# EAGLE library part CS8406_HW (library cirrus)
DIGITAL AUDIO INTERFACE TRANSMITTER (Hardware Mode) 192 kHz, AES3, S/PDIF-compatible Transmitter
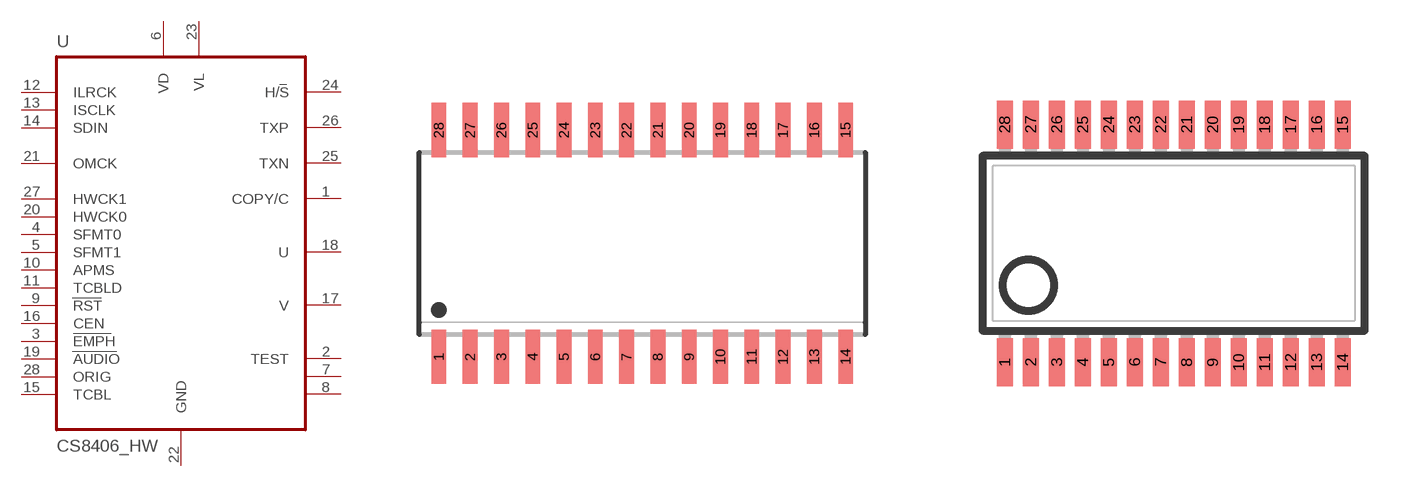
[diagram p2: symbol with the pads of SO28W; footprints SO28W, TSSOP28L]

Designator prefix U

## CS8406_HW-CSS  [SO28W]
1  COPY/C  in
2  TEST
3  EMPH  in
4  SFMT0  in
5  SFMT1  in
6  VD  pwr
7  TEST
8  TEST
9  RST  in
10  APMS  in
11  TCBLD  in
12  ILRCK
13  ISCLK
14  SDIN  in
15  TCBL
16  CEN  in
17  V  in
18  U  in
19  AUDIO  in
20  HWCK0  in
21  OMCK  in
22  GND  pwr
23  VL  pwr
24  H/S  in
25  TXN  out
26  TXP  out
27  HWCK1  in
28  ORIG  in

## CS8406_HW-CZZ  [TSSOP28L]
Pads as for SO28W

## Footprint SO28W (pad centres in mm)
SMALL OUTLINE INTEGRATED CIRCUIT wide body 7.5 mm/JEDEC MO-119AB
smd 0.6 x 2.2: 1 -8.255,-4.6; 2 -6.985,-4.6; 3 -5.715,-4.6; 4 -4.445,-4.6; 5 -3.175,-4.6; 6 -1.905,-4.6; 7 -0.635,-4.6; 8 0.635,-4.6; 9 1.905,-4.6; 10 3.175,-4.6; 11 4.445,-4.6; 12 5.715,-4.6; 13 6.985,-4.6; 14 8.255,-4.6; 15 8.255,4.6; 16 6.985,4.6; 17 5.715,4.6; 18 4.445,4.6; 19 3.175,4.6; 20 1.905,4.6; 21 0.635,4.6; 22 -0.635,4.6; 23 -1.905,4.6; 24 -3.175,4.6; 25 -4.445,4.6; 26 -5.715,4.6; 27 -6.985,4.6; 28 -8.255,4.6

## Footprint TSSOP28L (pad centres in mm)
Small Shrink Outline Package JEDEC MO-153
smd 0.4 x 1.2: 1 -3.575,-2.97; 2 -2.925,-2.97; 3 -2.275,-2.97; 4 -1.625,-2.97; 5 -0.975,-2.97; 6 -0.325,-2.97; 7 0.325,-2.97; 8 0.975,-2.97; 9 1.625,-2.97; 10 2.275,-2.97; 11 2.925,-2.97; 12 3.575,-2.97; 13 4.225,-2.97; 14 4.875,-2.97; 15 4.875,2.97; 16 4.225,2.97; 17 3.575,2.97; 18 2.925,2.97; 19 2.275,2.97; 20 1.625,2.97; 21 0.975,2.97; 22 0.325,2.97; 23 -0.325,2.97; 24 -0.975,2.97; 25 -1.625,2.97; 26 -2.275,2.97; 27 -2.925,2.97; 28 -3.575,2.97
